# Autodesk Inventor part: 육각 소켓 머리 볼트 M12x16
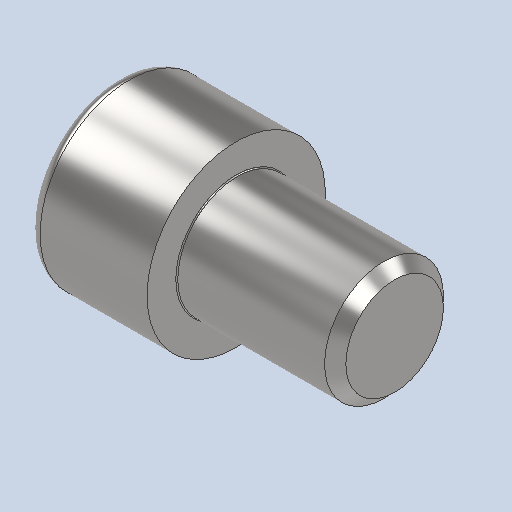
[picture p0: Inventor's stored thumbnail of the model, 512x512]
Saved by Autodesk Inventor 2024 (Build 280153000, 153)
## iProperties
Created: 2024-08
Part Number: 육각 소켓 머리 볼트 M12x16
Material: 강철, 연강
Description: 6각머리 태핑 나사
Document SubType Name: Modeling
Designer: user
Density: 7.85 g/cm^3
Appearance: 기본값
Author: jhkim
Sending System: Autodesk Inventor 2025
Preprocessor: ST-DEVELOPER v20
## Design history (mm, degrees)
feature "Solid1"
node "솔리드1"
